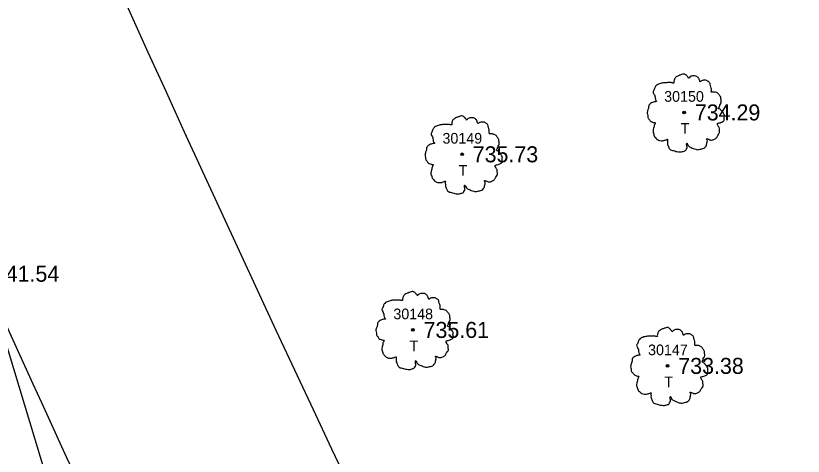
# Model space of a CAD drawing. Extents: x 1375131 to 1378678, y 999028 to 1004053.
# Drawn here: x 1376873.2 to 1376947, y 1002518 to 1002559.2 of the extents above; entities that cross this region are included whole.
import ezdxf

# ---------------------------------------------------------------- set-up
doc = ezdxf.new("R2010")
doc.units = 0
for name, color, linetype in [('RD_EX_Road', 7, 'Continuous'), ('RD_EX_RW', 7, 'Continuous'), ('RD_EX_SU_Elec', 7, 'Continuous'), ('RD_EX_TX_Road_ELEV', 7, 'Continuous'), ('RD_EX_TX_VEG_ELEV', 7, 'Continuous'), ('RD_EX_VEG', 7, 'Continuous'), ('RD_EX_VEG_txCode', 7, 'Continuous'), ('RD_HC_Cl', 7, 'Continuous'), ('RD_SMD_Locator', 7, 'Continuous')]:
    doc.layers.add(name, color=color, linetype=linetype)

msp = doc.modelspace()

# ---------------------------------------------------------------- linework, layer by layer
at = {"layer": 'RD_EX_Road'}
for points in [[(1377013.314, 1002264.907), (1376982.808, 1002315.683), (1376952.468, 1002370.341), (1376923.174, 1002424.32), (1376895.644, 1002480.03), (1376870.11, 1002535.049), (1376846.329, 1002588.864), (1376822.292, 1002645.031), (1376786.564, 1002736.458)], [(1376994.747, 1002253.913), (1376964.909, 1002306.463), (1376934.396, 1002359.987), (1376904.773, 1002415.485), (1376877.271, 1002471.511), (1376851.037, 1002526.893), (1376827.48, 1002581.62), (1376804.191, 1002637.821), (1376768.457, 1002728.838)]]:
    msp.add_spline(points, degree=3, dxfattribs=at)
at = {"layer": 'RD_EX_RW'}
for radius in [2767, 2833]:
    msp.add_arc((1379404.86, 1003700.108), radius, 200.269954, 211.131166, dxfattribs=at)
at = {"layer": 'RD_EX_SU_Elec'}
msp.add_line((1376829.238, 1002670.592), (1376932.6, 1002329.066), dxfattribs=at)
at = {"layer": 'RD_EX_VEG'}
for centre, radius in [((1376935.82, 1002550.156), 0.125), ((1376935.814, 1002550.147), 0.00005), ((1376915.002, 1002546.234), 0.125), ((1376914.996, 1002546.225), 0.00005), ((1376910.398, 1002529.786), 0.125), ((1376910.392, 1002529.777), 0.00005), ((1376934.272, 1002526.42), 0.125), ((1376934.266, 1002526.411), 0.00005)]:
    msp.add_circle(centre, radius, dxfattribs=at)
for points in [[(1376935.886, 1002553.74), (1376935.736, 1002553.752), (1376935.574, 1002553.702), (1376935.449, 1002553.652), (1376935.336, 1002553.615), (1376935.224, 1002553.565), (1376935.074, 1002553.477), (1376934.961, 1002553.377), (1376934.899, 1002553.252), (1376934.874, 1002553.14), (1376934.849, 1002553.002), (1376934.849, 1002552.915), (1376934.786, 1002552.902), (1376934.711, 1002552.915), (1376934.587, 1002552.952), (1376934.462, 1002552.952), (1376934.337, 1002552.952), (1376934.162, 1002552.94), (1376933.987, 1002552.94), (1376933.849, 1002552.915), (1376933.687, 1002552.89), (1376933.5, 1002552.828), (1376933.325, 1002552.765), (1376933.175, 1002552.64), (1376933.05, 1002552.403), (1376932.987, 1002552.228), (1376932.912, 1002552.103), (1376932.987, 1002551.878), (1376933.075, 1002551.703), (1376933.087, 1002551.603), (1376933.125, 1002551.391), (1376933.175, 1002551.278), (1376933.237, 1002551.178), (1376933.2, 1002551.166), (1376933.012, 1002551.141), (1376932.862, 1002551.091), (1376932.65, 1002550.978), (1376932.537, 1002550.866), (1376932.487, 1002550.703), (1376932.475, 1002550.529), (1376932.425, 1002550.429), (1376932.388, 1002550.291), (1376932.375, 1002550.254), (1376932.35, 1002550.091), (1376932.4, 1002549.866), (1376932.413, 1002549.691), (1376932.475, 1002549.579), (1376932.55, 1002549.492), (1376932.637, 1002549.367), (1376932.837, 1002549.254), (1376933, 1002549.204), (1376933.1, 1002549.192), (1376933.012, 1002548.942), (1376932.987, 1002548.767), (1376932.925, 1002548.567), (1376932.925, 1002548.529), (1376932.9, 1002548.292), (1376932.975, 1002548.13), (1376933.012, 1002547.942), (1376933.1, 1002547.83), (1376933.237, 1002547.68), (1376933.4, 1002547.567), (1376933.649, 1002547.505), (1376933.849, 1002547.517), (1376934.137, 1002547.605), (1376934.262, 1002547.642), (1376934.249, 1002547.555), (1376934.262, 1002547.367), (1376934.262, 1002547.155), (1376934.337, 1002546.993), (1376934.387, 1002546.855), (1376934.462, 1002546.73), (1376934.624, 1002546.618), (1376934.824, 1002546.58), (1376935.036, 1002546.505), (1376935.261, 1002546.468), (1376935.511, 1002546.455), (1376935.811, 1002546.53), (1376935.948, 1002546.593), (1376935.998, 1002546.68), (1376936.098, 1002546.868), (1376936.073, 1002546.98), (1376936.086, 1002547.28), (1376936.136, 1002547.192), (1376936.223, 1002547.018), (1376936.473, 1002546.868), (1376936.673, 1002546.78), (1376936.911, 1002546.705), (1376937.06, 1002546.668), (1376937.298, 1002546.705), (1376937.485, 1002546.743), (1376937.673, 1002546.805), (1376937.823, 1002546.943), (1376937.91, 1002547.08), (1376937.935, 1002547.217), (1376937.973, 1002547.405), (1376937.998, 1002547.492)], [(1376937.998, 1002547.492), (1376937.96, 1002547.58), (1376937.935, 1002547.705), (1376937.973, 1002547.692), (1376938.06, 1002547.667), (1376938.197, 1002547.605), (1376938.31, 1002547.567), (1376938.472, 1002547.58), (1376938.61, 1002547.63), (1376938.835, 1002547.767), (1376938.972, 1002548.005), (1376939.11, 1002548.205), (1376939.147, 1002548.367), (1376939.122, 1002548.479), (1376939.11, 1002548.729), (1376939.01, 1002548.854), (1376938.985, 1002548.917), (1376938.935, 1002549.117), (1376938.972, 1002549.142), (1376939.11, 1002549.167), (1376939.297, 1002549.229), (1376939.434, 1002549.292), (1376939.547, 1002549.379), (1376939.584, 1002549.492), (1376939.572, 1002549.691), (1376939.597, 1002549.891), (1376939.559, 1002549.966), (1376939.509, 1002550.041), (1376939.472, 1002550.141), (1376939.397, 1002550.216), (1376939.347, 1002550.291), (1376939.297, 1002550.341), (1376939.235, 1002550.416), (1376939.147, 1002550.479), (1376939.072, 1002550.504), (1376939.047, 1002550.579), (1376939.122, 1002550.678), (1376939.147, 1002550.728), (1376939.16, 1002550.841), (1376939.272, 1002551.016), (1376939.297, 1002551.216), (1376939.272, 1002551.428), (1376939.247, 1002551.566), (1376939.172, 1002551.703), (1376939.072, 1002551.828), (1376939.01, 1002551.915), (1376938.922, 1002551.978), (1376938.76, 1002552.04), (1376938.635, 1002552.065), (1376938.46, 1002552.065), (1376938.36, 1002552.09), (1376938.372, 1002552.115), (1376938.372, 1002552.19), (1376938.372, 1002552.328), (1376938.335, 1002552.553), (1376938.26, 1002552.803), (1376938.26, 1002552.815), (1376938.21, 1002552.94), (1376938.098, 1002553.04), (1376938.01, 1002553.09), (1376937.91, 1002553.152), (1376937.785, 1002553.165), (1376937.635, 1002553.165), (1376937.498, 1002553.14), (1376937.398, 1002553.09), (1376937.31, 1002553.027), (1376937.273, 1002553.102), (1376937.223, 1002553.252), (1376937.198, 1002553.327), (1376937.123, 1002553.415), (1376937.011, 1002553.515), (1376936.786, 1002553.577), (1376936.473, 1002553.54), (1376936.323, 1002553.44), (1376936.248, 1002553.352), (1376936.223, 1002553.415), (1376936.123, 1002553.515), (1376936.073, 1002553.602), (1376935.986, 1002553.665), (1376935.911, 1002553.715), (1376935.861, 1002553.74)], [(1376915.068, 1002549.818), (1376914.918, 1002549.83), (1376914.756, 1002549.78), (1376914.631, 1002549.73), (1376914.518, 1002549.693), (1376914.406, 1002549.643), (1376914.256, 1002549.555), (1376914.143, 1002549.455), (1376914.081, 1002549.33), (1376914.056, 1002549.218), (1376914.031, 1002549.08), (1376914.031, 1002548.993), (1376913.968, 1002548.98), (1376913.893, 1002548.993), (1376913.769, 1002549.03), (1376913.644, 1002549.03), (1376913.519, 1002549.03), (1376913.344, 1002549.018), (1376913.169, 1002549.018), (1376913.031, 1002548.993), (1376912.869, 1002548.968), (1376912.682, 1002548.906), (1376912.507, 1002548.843), (1376912.357, 1002548.718), (1376912.232, 1002548.481), (1376912.169, 1002548.306), (1376912.094, 1002548.181), (1376912.169, 1002547.956), (1376912.257, 1002547.781), (1376912.269, 1002547.681), (1376912.307, 1002547.469), (1376912.357, 1002547.356), (1376912.419, 1002547.256), (1376912.382, 1002547.244), (1376912.194, 1002547.219), (1376912.044, 1002547.169), (1376911.832, 1002547.056), (1376911.719, 1002546.944), (1376911.669, 1002546.781), (1376911.657, 1002546.607), (1376911.607, 1002546.507), (1376911.57, 1002546.369), (1376911.557, 1002546.332), (1376911.532, 1002546.169), (1376911.582, 1002545.944), (1376911.595, 1002545.769), (1376911.657, 1002545.657), (1376911.732, 1002545.57), (1376911.819, 1002545.445), (1376912.019, 1002545.332), (1376912.182, 1002545.282), (1376912.282, 1002545.27), (1376912.194, 1002545.02), (1376912.169, 1002544.845), (1376912.107, 1002544.645), (1376912.107, 1002544.607), (1376912.082, 1002544.37), (1376912.157, 1002544.208), (1376912.194, 1002544.02), (1376912.282, 1002543.908), (1376912.419, 1002543.758), (1376912.582, 1002543.645), (1376912.831, 1002543.583), (1376913.031, 1002543.595), (1376913.319, 1002543.683), (1376913.444, 1002543.72), (1376913.431, 1002543.633), (1376913.444, 1002543.445), (1376913.444, 1002543.233), (1376913.519, 1002543.071), (1376913.569, 1002542.933), (1376913.644, 1002542.808), (1376913.806, 1002542.696), (1376914.006, 1002542.658), (1376914.218, 1002542.583), (1376914.443, 1002542.546), (1376914.693, 1002542.533), (1376914.993, 1002542.608), (1376915.13, 1002542.671), (1376915.18, 1002542.758), (1376915.28, 1002542.946), (1376915.255, 1002543.058), (1376915.268, 1002543.358), (1376915.318, 1002543.27), (1376915.405, 1002543.096), (1376915.655, 1002542.946), (1376915.855, 1002542.858), (1376916.093, 1002542.783), (1376916.242, 1002542.746), (1376916.48, 1002542.783), (1376916.667, 1002542.821), (1376916.855, 1002542.883), (1376917.005, 1002543.021), (1376917.092, 1002543.158), (1376917.117, 1002543.295), (1376917.155, 1002543.483), (1376917.18, 1002543.57)], [(1376917.18, 1002543.57), (1376917.142, 1002543.658), (1376917.117, 1002543.783), (1376917.155, 1002543.77), (1376917.242, 1002543.745), (1376917.379, 1002543.683), (1376917.492, 1002543.645), (1376917.654, 1002543.658), (1376917.792, 1002543.708), (1376918.017, 1002543.845), (1376918.154, 1002544.083), (1376918.292, 1002544.283), (1376918.329, 1002544.445), (1376918.304, 1002544.557), (1376918.292, 1002544.807), (1376918.192, 1002544.932), (1376918.167, 1002544.995), (1376918.117, 1002545.195), (1376918.154, 1002545.22), (1376918.292, 1002545.245), (1376918.479, 1002545.307), (1376918.616, 1002545.37), (1376918.729, 1002545.457), (1376918.766, 1002545.57), (1376918.754, 1002545.769), (1376918.779, 1002545.969), (1376918.741, 1002546.044), (1376918.691, 1002546.119), (1376918.654, 1002546.219), (1376918.579, 1002546.294), (1376918.529, 1002546.369), (1376918.479, 1002546.419), (1376918.417, 1002546.494), (1376918.329, 1002546.557), (1376918.254, 1002546.582), (1376918.229, 1002546.657), (1376918.304, 1002546.756), (1376918.329, 1002546.806), (1376918.342, 1002546.919), (1376918.454, 1002547.094), (1376918.479, 1002547.294), (1376918.454, 1002547.506), (1376918.429, 1002547.644), (1376918.354, 1002547.781), (1376918.254, 1002547.906), (1376918.192, 1002547.993), (1376918.104, 1002548.056), (1376917.942, 1002548.118), (1376917.817, 1002548.143), (1376917.642, 1002548.143), (1376917.542, 1002548.168), (1376917.554, 1002548.193), (1376917.554, 1002548.268), (1376917.554, 1002548.406), (1376917.517, 1002548.631), (1376917.442, 1002548.881), (1376917.442, 1002548.893), (1376917.392, 1002549.018), (1376917.28, 1002549.118), (1376917.192, 1002549.168), (1376917.092, 1002549.23), (1376916.967, 1002549.243), (1376916.817, 1002549.243), (1376916.68, 1002549.218), (1376916.58, 1002549.168), (1376916.492, 1002549.105), (1376916.455, 1002549.18), (1376916.405, 1002549.33), (1376916.38, 1002549.405), (1376916.305, 1002549.493), (1376916.193, 1002549.593), (1376915.968, 1002549.655), (1376915.655, 1002549.618), (1376915.505, 1002549.518), (1376915.43, 1002549.43), (1376915.405, 1002549.493), (1376915.305, 1002549.593), (1376915.255, 1002549.68), (1376915.168, 1002549.743), (1376915.093, 1002549.793), (1376915.043, 1002549.818)], [(1376910.464, 1002533.37), (1376910.314, 1002533.382), (1376910.152, 1002533.332), (1376910.027, 1002533.282), (1376909.914, 1002533.245), (1376909.802, 1002533.195), (1376909.652, 1002533.107), (1376909.539, 1002533.007), (1376909.477, 1002532.882), (1376909.452, 1002532.77), (1376909.427, 1002532.632), (1376909.427, 1002532.545), (1376909.364, 1002532.532), (1376909.289, 1002532.545), (1376909.165, 1002532.582), (1376909.04, 1002532.582), (1376908.915, 1002532.582), (1376908.74, 1002532.57), (1376908.565, 1002532.57), (1376908.427, 1002532.545), (1376908.265, 1002532.52), (1376908.078, 1002532.458), (1376907.903, 1002532.395), (1376907.753, 1002532.27), (1376907.628, 1002532.033), (1376907.565, 1002531.858), (1376907.49, 1002531.733), (1376907.565, 1002531.508), (1376907.653, 1002531.333), (1376907.665, 1002531.233), (1376907.703, 1002531.021), (1376907.753, 1002530.908), (1376907.815, 1002530.808), (1376907.778, 1002530.796), (1376907.59, 1002530.771), (1376907.44, 1002530.721), (1376907.228, 1002530.608), (1376907.115, 1002530.496), (1376907.065, 1002530.333), (1376907.053, 1002530.159), (1376907.003, 1002530.059), (1376906.966, 1002529.921), (1376906.953, 1002529.884), (1376906.928, 1002529.721), (1376906.978, 1002529.496), (1376906.991, 1002529.321), (1376907.053, 1002529.209), (1376907.128, 1002529.122), (1376907.215, 1002528.997), (1376907.415, 1002528.884), (1376907.578, 1002528.834), (1376907.678, 1002528.822), (1376907.59, 1002528.572), (1376907.565, 1002528.397), (1376907.503, 1002528.197), (1376907.503, 1002528.159), (1376907.478, 1002527.922), (1376907.553, 1002527.76), (1376907.59, 1002527.572), (1376907.678, 1002527.46), (1376907.815, 1002527.31), (1376907.978, 1002527.197), (1376908.227, 1002527.135), (1376908.427, 1002527.147), (1376908.715, 1002527.235), (1376908.84, 1002527.272), (1376908.827, 1002527.185), (1376908.84, 1002526.997), (1376908.84, 1002526.785), (1376908.915, 1002526.623), (1376908.965, 1002526.485), (1376909.04, 1002526.36), (1376909.202, 1002526.248), (1376909.402, 1002526.21), (1376909.614, 1002526.135), (1376909.839, 1002526.098), (1376910.089, 1002526.085), (1376910.389, 1002526.16), (1376910.526, 1002526.223), (1376910.576, 1002526.31), (1376910.676, 1002526.498), (1376910.651, 1002526.61), (1376910.664, 1002526.91), (1376910.714, 1002526.822), (1376910.801, 1002526.648), (1376911.051, 1002526.498), (1376911.251, 1002526.41), (1376911.489, 1002526.335), (1376911.638, 1002526.298), (1376911.876, 1002526.335), (1376912.063, 1002526.373), (1376912.251, 1002526.435), (1376912.401, 1002526.573), (1376912.488, 1002526.71), (1376912.513, 1002526.847), (1376912.551, 1002527.035), (1376912.576, 1002527.122)], [(1376912.576, 1002527.122), (1376912.538, 1002527.21), (1376912.513, 1002527.335), (1376912.551, 1002527.322), (1376912.638, 1002527.297), (1376912.775, 1002527.235), (1376912.888, 1002527.197), (1376913.05, 1002527.21), (1376913.188, 1002527.26), (1376913.413, 1002527.397), (1376913.55, 1002527.635), (1376913.688, 1002527.835), (1376913.725, 1002527.997), (1376913.7, 1002528.109), (1376913.688, 1002528.359), (1376913.588, 1002528.484), (1376913.563, 1002528.547), (1376913.513, 1002528.747), (1376913.55, 1002528.772), (1376913.688, 1002528.797), (1376913.875, 1002528.859), (1376914.012, 1002528.922), (1376914.125, 1002529.009), (1376914.162, 1002529.122), (1376914.15, 1002529.321), (1376914.175, 1002529.521), (1376914.137, 1002529.596), (1376914.087, 1002529.671), (1376914.05, 1002529.771), (1376913.975, 1002529.846), (1376913.925, 1002529.921), (1376913.875, 1002529.971), (1376913.813, 1002530.046), (1376913.725, 1002530.109), (1376913.65, 1002530.134), (1376913.625, 1002530.209), (1376913.7, 1002530.308), (1376913.725, 1002530.358), (1376913.738, 1002530.471), (1376913.85, 1002530.646), (1376913.875, 1002530.846), (1376913.85, 1002531.058), (1376913.825, 1002531.196), (1376913.75, 1002531.333), (1376913.65, 1002531.458), (1376913.588, 1002531.545), (1376913.5, 1002531.608), (1376913.338, 1002531.67), (1376913.213, 1002531.695), (1376913.038, 1002531.695), (1376912.938, 1002531.72), (1376912.95, 1002531.745), (1376912.95, 1002531.82), (1376912.95, 1002531.958), (1376912.913, 1002532.183), (1376912.838, 1002532.433), (1376912.838, 1002532.445), (1376912.788, 1002532.57), (1376912.676, 1002532.67), (1376912.588, 1002532.72), (1376912.488, 1002532.782), (1376912.363, 1002532.795), (1376912.213, 1002532.795), (1376912.076, 1002532.77), (1376911.976, 1002532.72), (1376911.888, 1002532.657), (1376911.851, 1002532.732), (1376911.801, 1002532.882), (1376911.776, 1002532.957), (1376911.701, 1002533.045), (1376911.589, 1002533.145), (1376911.364, 1002533.207), (1376911.051, 1002533.17), (1376910.901, 1002533.07), (1376910.826, 1002532.982), (1376910.801, 1002533.045), (1376910.701, 1002533.145), (1376910.651, 1002533.232), (1376910.564, 1002533.295), (1376910.489, 1002533.345), (1376910.439, 1002533.37)], [(1376934.338, 1002530.004), (1376934.188, 1002530.016), (1376934.026, 1002529.966), (1376933.901, 1002529.916), (1376933.788, 1002529.879), (1376933.676, 1002529.829), (1376933.526, 1002529.741), (1376933.413, 1002529.641), (1376933.351, 1002529.516), (1376933.326, 1002529.404), (1376933.301, 1002529.266), (1376933.301, 1002529.179), (1376933.238, 1002529.166), (1376933.163, 1002529.179), (1376933.039, 1002529.216), (1376932.914, 1002529.216), (1376932.789, 1002529.216), (1376932.614, 1002529.204), (1376932.439, 1002529.204), (1376932.301, 1002529.179), (1376932.139, 1002529.154), (1376931.952, 1002529.092), (1376931.777, 1002529.029), (1376931.627, 1002528.904), (1376931.502, 1002528.667), (1376931.439, 1002528.492), (1376931.364, 1002528.367), (1376931.439, 1002528.142), (1376931.527, 1002527.967), (1376931.539, 1002527.867), (1376931.577, 1002527.655), (1376931.627, 1002527.542), (1376931.689, 1002527.442), (1376931.652, 1002527.43), (1376931.464, 1002527.405), (1376931.314, 1002527.355), (1376931.102, 1002527.242), (1376930.989, 1002527.13), (1376930.939, 1002526.967), (1376930.927, 1002526.793), (1376930.877, 1002526.693), (1376930.84, 1002526.555), (1376930.827, 1002526.518), (1376930.802, 1002526.355), (1376930.852, 1002526.13), (1376930.865, 1002525.955), (1376930.927, 1002525.843), (1376931.002, 1002525.756), (1376931.089, 1002525.631), (1376931.289, 1002525.518), (1376931.452, 1002525.468), (1376931.552, 1002525.456), (1376931.464, 1002525.206), (1376931.439, 1002525.031), (1376931.377, 1002524.831), (1376931.377, 1002524.793), (1376931.352, 1002524.556), (1376931.427, 1002524.394), (1376931.464, 1002524.206), (1376931.552, 1002524.094), (1376931.689, 1002523.944), (1376931.852, 1002523.831), (1376932.101, 1002523.769), (1376932.301, 1002523.781), (1376932.589, 1002523.869), (1376932.714, 1002523.906), (1376932.701, 1002523.819), (1376932.714, 1002523.631), (1376932.714, 1002523.419), (1376932.789, 1002523.257), (1376932.839, 1002523.119), (1376932.914, 1002522.994), (1376933.076, 1002522.882), (1376933.276, 1002522.844), (1376933.488, 1002522.769), (1376933.713, 1002522.732), (1376933.963, 1002522.719), (1376934.263, 1002522.794), (1376934.4, 1002522.857), (1376934.45, 1002522.944), (1376934.55, 1002523.132), (1376934.525, 1002523.244), (1376934.538, 1002523.544), (1376934.588, 1002523.456), (1376934.675, 1002523.282), (1376934.925, 1002523.132), (1376935.125, 1002523.044), (1376935.363, 1002522.969), (1376935.512, 1002522.932), (1376935.75, 1002522.969), (1376935.937, 1002523.007), (1376936.125, 1002523.069), (1376936.275, 1002523.207), (1376936.362, 1002523.344), (1376936.387, 1002523.481), (1376936.425, 1002523.669), (1376936.45, 1002523.756)], [(1376936.45, 1002523.756), (1376936.412, 1002523.844), (1376936.387, 1002523.969), (1376936.425, 1002523.956), (1376936.512, 1002523.931), (1376936.649, 1002523.869), (1376936.762, 1002523.831), (1376936.924, 1002523.844), (1376937.062, 1002523.894), (1376937.287, 1002524.031), (1376937.424, 1002524.269), (1376937.562, 1002524.469), (1376937.599, 1002524.631), (1376937.574, 1002524.743), (1376937.562, 1002524.993), (1376937.462, 1002525.118), (1376937.437, 1002525.181), (1376937.387, 1002525.381), (1376937.424, 1002525.406), (1376937.562, 1002525.431), (1376937.749, 1002525.493), (1376937.886, 1002525.556), (1376937.999, 1002525.643), (1376938.036, 1002525.756), (1376938.024, 1002525.955), (1376938.049, 1002526.155), (1376938.011, 1002526.23), (1376937.961, 1002526.305), (1376937.924, 1002526.405), (1376937.849, 1002526.48), (1376937.799, 1002526.555), (1376937.749, 1002526.605), (1376937.687, 1002526.68), (1376937.599, 1002526.743), (1376937.524, 1002526.768), (1376937.499, 1002526.843), (1376937.574, 1002526.942), (1376937.599, 1002526.992), (1376937.612, 1002527.105), (1376937.724, 1002527.28), (1376937.749, 1002527.48), (1376937.724, 1002527.692), (1376937.699, 1002527.83), (1376937.624, 1002527.967), (1376937.524, 1002528.092), (1376937.462, 1002528.179), (1376937.374, 1002528.242), (1376937.212, 1002528.304), (1376937.087, 1002528.329), (1376936.912, 1002528.329), (1376936.812, 1002528.354), (1376936.824, 1002528.379), (1376936.824, 1002528.454), (1376936.824, 1002528.592), (1376936.787, 1002528.817), (1376936.712, 1002529.067), (1376936.712, 1002529.079), (1376936.662, 1002529.204), (1376936.55, 1002529.304), (1376936.462, 1002529.354), (1376936.362, 1002529.416), (1376936.237, 1002529.429), (1376936.087, 1002529.429), (1376935.95, 1002529.404), (1376935.85, 1002529.354), (1376935.762, 1002529.291), (1376935.725, 1002529.366), (1376935.675, 1002529.516), (1376935.65, 1002529.591), (1376935.575, 1002529.679), (1376935.463, 1002529.779), (1376935.238, 1002529.841), (1376934.925, 1002529.804), (1376934.775, 1002529.704), (1376934.7, 1002529.616), (1376934.675, 1002529.679), (1376934.575, 1002529.779), (1376934.525, 1002529.866), (1376934.438, 1002529.929), (1376934.363, 1002529.979), (1376934.313, 1002530.004)]]:
    msp.add_spline(points, degree=3, dxfattribs=at)
at = {"layer": 'RD_HC_Cl'}
msp.add_arc((1379404.86, 1003700.108), 2800, 200.269954, 211.131166, dxfattribs=at)
at = {"layer": 'RD_SMD_Locator'}
for centre in [(1376935.82, 1002550.156), (1376915.002, 1002546.234), (1376910.398, 1002529.786), (1376934.272, 1002526.42)]:
    msp.add_circle(centre, 0.075, dxfattribs=at)

# ---------------------------------------------------------------- texts
at = {"layer": 'RD_EX_TX_Road_ELEV'}
msp.add_text('741.54', height=1.5, dxfattribs=at).set_placement((1376871.11, 1002534.299))
at = {"layer": 'RD_EX_TX_VEG_ELEV'}
for s, p in [('734.29', (1376936.82, 1002549.406)), ('735.73', (1376916.002, 1002545.484)), ('735.61', (1376911.398, 1002529.036)), ('733.38', (1376935.272, 1002525.67))]:
    msp.add_text(s, height=1.5, dxfattribs=at).set_placement(p)
at = {"layer": 'RD_EX_VEG_txCode'}
for s, p in [('30150', (1376933.946, 1002551.156)), ('T', (1376935.497, 1002548.156)), ('30149', (1376913.167, 1002547.234)), ('T', (1376914.679, 1002544.234)), ('30148', (1376908.563, 1002530.786)), ('T', (1376910.075, 1002527.786)), ('30147', (1376932.437, 1002527.42)), ('T', (1376933.949, 1002524.42))]:
    msp.add_text(s, height=1, dxfattribs=at).set_placement(p)

doc.saveas('drawing.dxf')
